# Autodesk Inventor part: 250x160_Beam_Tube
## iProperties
Shininess: 64.0
Length Units: 11269
Angle Units: 11279
Time Units: 11290
Mass Units: 11283
Length Display Precision: 3
Angle Display Precision: 2
Compacted: True
Part Number: 250x160_Beam_Tube
Document SubType Name: Modeling
Created: 2004-07
Designer: John Blackburn
Manufacturer: Standard
Standards Organization: Custom
Density: 0.0
Volumn: 0.0
Area: 0.0
PropertySet Name: Model Information
Control State: 0
Master: False
Checked Out: False
Author: John Blackburn
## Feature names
1. Extrusion1
